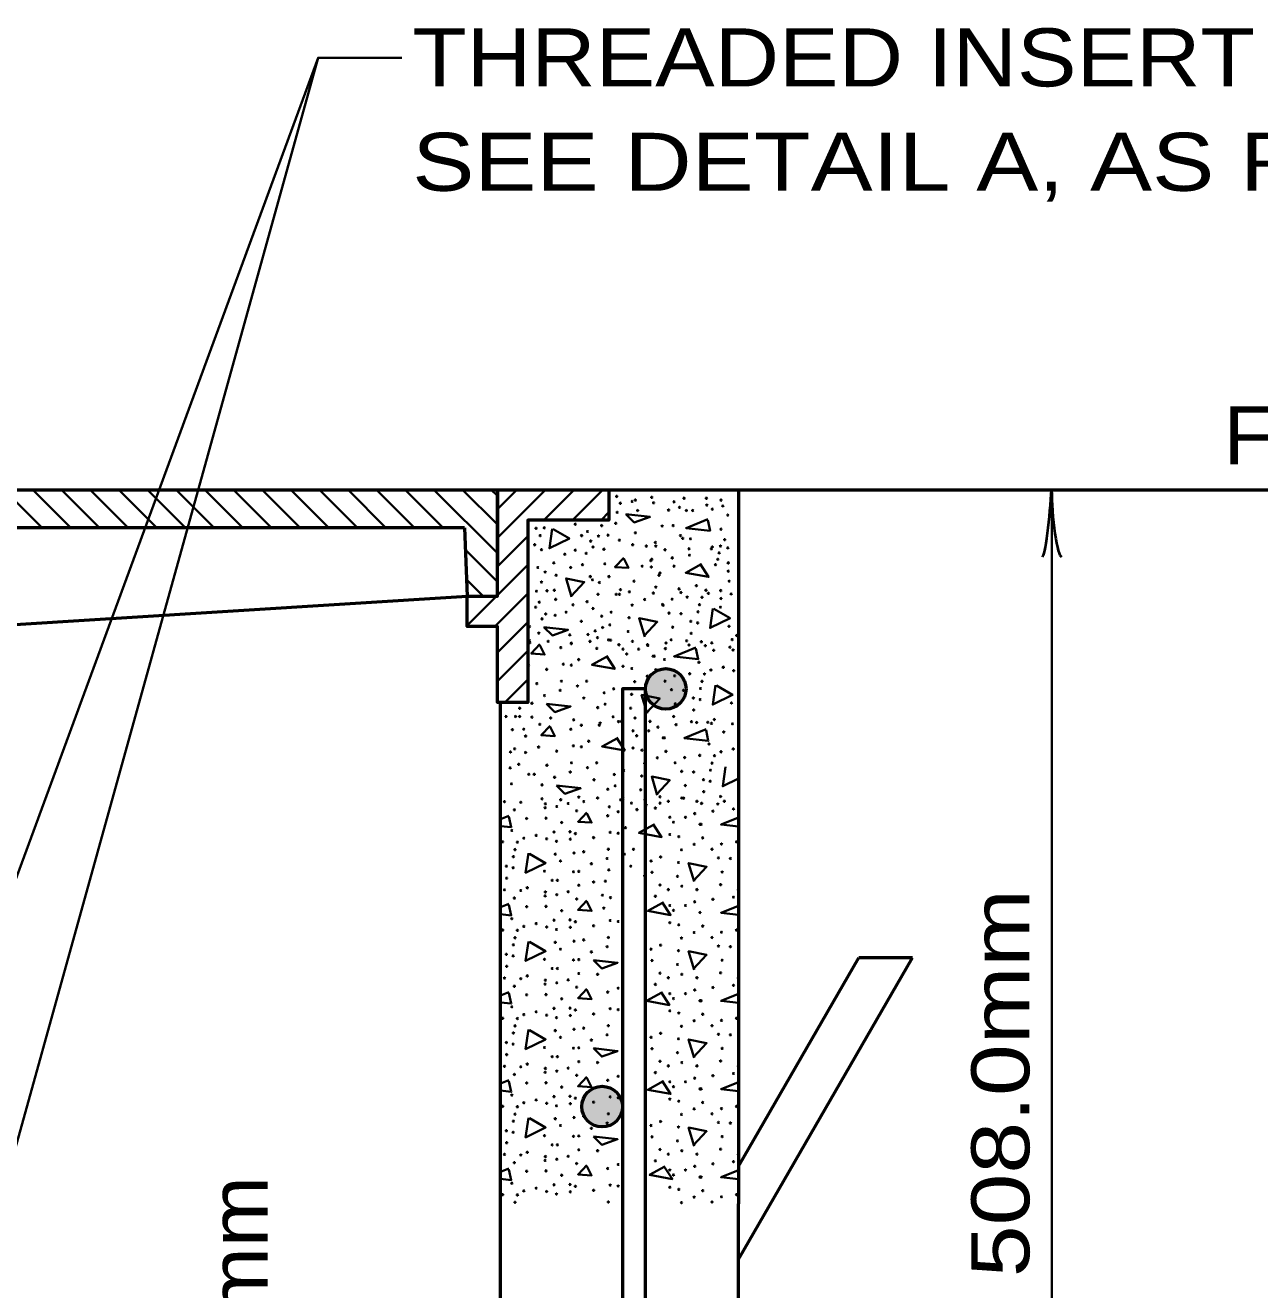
# Model space of a CAD drawing. Extents: x 918 to 1774, y -8 to 536.
# Drawn here: x 1103.6 to 1167.4, y 193.7 to 259.1 of the extents above; entities that cross this region are included whole.
import ezdxf

# ---------------------------------------------------------------- set-up
doc = ezdxf.new("R2010")
doc.units = 0
doc.header["$LTSCALE"] = 1.2
doc.layers.add('1', color=7, linetype='Continuous', lineweight=35)

msp = doc.modelspace()

# ---------------------------------------------------------------- hatches: boundary and pattern name
at = {"layer": '1'}
for points in [[(1135.628, 224.745, 1), (1137.721, 224.745, 1)], [(1132.329, 203.145, 1), (1134.433, 203.145, 1)]]:
    msp.add_hatch(color=256, dxfattribs=at).paths.add_polyline_path(points)

# ---------------------------------------------------------------- linework, layer by layer
for p, q in [((1118.692, 257.384), (1123.028, 257.384)), ((1102.459, 235.047), (1104.424, 233.082)), ((1103.941, 235.047), (1105.905, 233.082)), ((1105.423, 235.047), (1107.387, 233.082)), ((1106.905, 235.047), (1108.87, 233.082)), ((1108.387, 235.047), (1110.351, 233.082)), ((1109.868, 235.047), (1111.833, 233.082)), ((1111.351, 235.047), (1113.315, 233.082)), ((1112.832, 235.047), (1114.797, 233.082)), ((1114.314, 235.047), (1116.279, 233.082)), ((1115.796, 235.047), (1117.761, 233.082)), ((1117.278, 235.047), (1119.243, 233.082)), ((1118.76, 235.047), (1120.725, 233.082)), ((1120.243, 235.047), (1122.207, 233.082)), ((1121.724, 235.047), (1123.689, 233.082)), ((1123.206, 235.047), (1125.171, 233.082)), ((1124.688, 235.047), (1127.967, 231.768)), ((1126.17, 235.047), (1127.967, 233.25)), ((1127.653, 235.047), (1127.967, 234.731)), ((1127.967, 234.04), (1128.974, 235.047)), ((1127.967, 232.558), (1130.456, 235.047)), ((1130.366, 233.475), (1131.938, 235.047)), ((1131.848, 233.475), (1133.42, 235.047)), ((1133.33, 233.475), (1133.731, 233.876)), ((1127.967, 231.076), (1129.539, 232.648)), ((1126.303, 231.95), (1127.967, 230.285)), ((1127.967, 229.594), (1129.539, 231.166)), ((1126.362, 230.408), (1127.226, 229.545)), ((1126.396, 228.022), (1127.918, 229.545)), ((1127.828, 227.973), (1129.539, 229.684)), ((1127.967, 226.63), (1129.539, 228.202)), ((1127.967, 225.148), (1129.539, 226.72)), ((1128.345, 224.043), (1129.539, 225.238)), ((1128.563, 218.189), (1128.128, 218.013)), ((1128.563, 213.629), (1128.128, 213.453)), ((1128.563, 209.069), (1128.128, 208.893)), ((1128.563, 204.509), (1128.128, 204.333)), ((1128.563, 199.949), (1128.128, 199.773))]:
    msp.add_line(p, q, dxfattribs=at)
at = {"layer": '1', "lineweight": 53}
for p, q in [((1072.952, 235.047), (1127.967, 235.047)), ((1127.967, 235.047), (1140.428, 235.047)), ((1127.967, 235.047), (1127.967, 231.117)), ((1140.428, 235.047), (1140.428, 198.122)), ((1140.428, 235.047), (1199.62, 235.047)), ((1126.26, 233.082), (1126.396, 229.545)), ((1101.426, 227.973), (1126.396, 229.545)), ((1128.128, 198.122), (1128.128, 224.043)), ((1140.428, 195.243), (1149.428, 210.843)), ((1140.428, 200.046), (1146.657, 210.843)), ((1149.428, 210.843), (1146.657, 210.843)), ((1128.128, 159.172), (1128.128, 198.122)), ((1140.428, 159.172), (1140.428, 198.122))]:
    msp.add_line(p, q, dxfattribs=at)
at = {"layer": '1'}
for points in [[(1101.54, 210.795), (1118.692, 257.384), (1101.575, 195.743)], [(1156.628, 235.047), (1156.628, 170.643), (1156.628, 158.067), (1156.628, 146.075), (1156.628, 108.575)], [(1138.849, 233.52), (1137.721, 233.064), (1138.968, 232.92), (1138.849, 233.472)], [(1130.848, 233.003), (1131.688, 232.523), (1130.656, 232.019), (1130.8, 233.027)], [(1134.504, 231.528), (1134.048, 231.048), (1134.744, 231), (1134.504, 231.48)], [(1138.502, 231.187), (1137.71, 230.755), (1138.886, 230.539), (1138.454, 231.211)], [(1131.807, 229.5), (1131.519, 230.46), (1132.455, 230.268), (1131.783, 229.548)], [(1139.161, 228.881), (1140.001, 228.401), (1138.969, 227.897), (1139.113, 228.905)], [(1135.585, 227.441), (1135.297, 228.401), (1136.233, 228.209), (1135.561, 227.489)], [(1130.17, 227.052), (1129.715, 226.572), (1130.41, 226.524), (1130.17, 227.004)], [(1138.235, 226.884), (1137.107, 226.428), (1138.355, 226.284), (1138.235, 226.836)], [(1133.65, 226.428), (1132.859, 225.996), (1134.034, 225.78), (1133.602, 226.452)], [(1139.291, 224.916), (1140.13, 224.436), (1139.099, 223.932), (1139.243, 224.94)], [(1135.715, 223.476), (1135.427, 224.436), (1136.362, 224.244), (1135.691, 223.524)], [(1130.69, 222.828), (1130.234, 222.348), (1130.93, 222.3), (1130.69, 222.78)], [(1138.754, 222.66), (1137.626, 222.204), (1138.874, 222.06), (1138.754, 222.612)], [(1134.17, 222.204), (1133.378, 221.772), (1134.554, 221.556), (1134.122, 222.228)], [(1140.428, 220.104), (1139.618, 219.708), (1139.762, 220.716)], [(1136.234, 219.252), (1135.946, 220.212), (1136.882, 220.02), (1136.21, 219.3)], [(1128.128, 217.653), (1128.683, 217.589), (1128.563, 218.141)], [(1132.595, 218.357), (1132.139, 217.877), (1132.835, 217.829), (1132.595, 218.309)], [(1136.075, 217.733), (1135.283, 217.301), (1136.459, 217.085), (1136.027, 217.757)], [(1140.428, 218.095), (1139.531, 217.733), (1140.428, 217.629)], [(1129.619, 216.221), (1130.459, 215.741), (1129.427, 215.237), (1129.571, 216.245)], [(1138.139, 214.781), (1137.851, 215.741), (1138.787, 215.549), (1138.115, 214.829)], [(1128.128, 213.093), (1128.683, 213.029), (1128.563, 213.581)], [(1132.595, 213.797), (1132.139, 213.317), (1132.835, 213.269), (1132.595, 213.749)], [(1136.536, 213.696), (1135.744, 213.264), (1136.92, 213.048), (1136.488, 213.72)], [(1140.428, 213.535), (1139.531, 213.173), (1140.428, 213.069)], [(1129.619, 211.661), (1130.459, 211.181), (1129.427, 210.677), (1129.571, 211.685)], [(1138.139, 210.221), (1137.851, 211.181), (1138.787, 210.989), (1138.115, 210.269)], [(1132.595, 209.237), (1132.139, 208.757), (1132.835, 208.709), (1132.595, 209.189)], [(1128.128, 208.533), (1128.683, 208.469), (1128.563, 209.021)], [(1136.475, 209.044), (1135.683, 208.612), (1136.859, 208.396), (1136.427, 209.068)], [(1140.428, 208.975), (1139.531, 208.613), (1140.428, 208.509)], [(1129.619, 207.101), (1130.459, 206.621), (1129.427, 206.117), (1129.571, 207.125)], [(1138.139, 205.661), (1137.851, 206.621), (1138.787, 206.429), (1138.115, 205.709)], [(1132.595, 204.677), (1132.139, 204.197), (1132.835, 204.149), (1132.595, 204.629)], [(1128.128, 203.973), (1128.683, 203.909), (1128.563, 204.461)], [(1136.536, 204.453), (1135.744, 204.021), (1136.92, 203.805), (1136.488, 204.477)], [(1140.428, 204.415), (1139.531, 204.053), (1140.428, 203.949)], [(1129.619, 202.541), (1130.459, 202.061), (1129.427, 201.557), (1129.571, 202.565)], [(1138.139, 201.101), (1137.851, 202.061), (1138.787, 201.869), (1138.115, 201.149)], [(1132.595, 200.117), (1132.139, 199.637), (1132.835, 199.589), (1132.595, 200.069)], [(1128.128, 199.413), (1128.683, 199.349), (1128.563, 199.901)], [(1136.629, 200.047), (1135.837, 199.615), (1137.013, 199.399), (1136.581, 200.071)], [(1140.428, 199.855), (1139.531, 199.493), (1140.428, 199.389)]]:
    msp.add_lwpolyline(points, dxfattribs=at)
at = {"layer": '1', "lineweight": 53}
for points in [[(1133.731, 235.047), (1133.731, 233.475), (1129.539, 233.475), (1129.539, 224.043), (1127.967, 224.043), (1127.967, 227.973), (1126.396, 227.973), (1126.396, 229.545), (1127.967, 229.545), (1127.967, 235.047)], [(1126.26, 233.082), (1101.778, 233.082), (1101.426, 227.973), (1099.493, 227.973), (1099.141, 233.082)]]:
    msp.add_lwpolyline(points, dxfattribs=at)
at = {"layer": '1'}
for points in [[(1134.616, 233.787), (1135.864, 233.643), (1135.048, 233.355)], [(1130.377, 227.945), (1131.625, 227.8), (1130.809, 227.513)], [(1130.506, 223.98), (1131.755, 223.836), (1130.938, 223.548)], [(1131.026, 219.756), (1132.274, 219.612), (1131.458, 219.324)], [(1132.931, 210.725), (1134.179, 210.581), (1133.363, 210.293)], [(1132.931, 206.165), (1134.179, 206.021), (1133.363, 205.733)], [(1132.931, 201.605), (1134.179, 201.461), (1133.363, 201.173)]]:
    msp.add_lwpolyline(points, close=True, dxfattribs=at)
at = {"layer": '1', "lineweight": 53}
msp.add_lwpolyline([(1135.628, 152.043), (1135.628, 224.745), (1134.428, 224.745), (1134.428, 153.243), (1110.428, 153.243), (1110.428, 152.043)], close=True, dxfattribs=at)
at = {"layer": '1'}
for centre in [(1134.136, 234.698), (1134.324, 234.345), (1134.936, 234.439), (1135.101, 234.51), (1135.949, 234.651), (1136.043, 234.369), (1137.103, 234.416), (1137.385, 234.133), (1137.621, 234.604), (1138.775, 234.604), (1138.798, 234.251), (1139.528, 234.51), (1139.623, 234.204), (1134.159, 233.874), (1135.219, 233.968), (1136.82, 233.992), (1137.739, 233.968), (1138.068, 233.968), (1139.081, 234.039), (1139.882, 233.732), (1129.967, 233.049), (1130.391, 233.073), (1131.993, 233.261), (1132.628, 232.884), (1133.358, 233.191), (1134.088, 233.308), (1135.101, 232.814), (1136.49, 233.167), (1137.056, 233.191), (1139.528, 233.002), (1129.897, 232.201), (1130.179, 232.672), (1132.322, 232.672), (1132.793, 232.39), (1132.911, 232.083), (1133.194, 232.649), (1133.688, 232.696), (1134.277, 232.437), (1134.96, 232.201), (1135.666, 232.131), (1136.137, 232.319), (1136.161, 232.131), (1137.432, 232.672), (1137.55, 232.531), (1137.951, 232.508), (1139.081, 232.083), (1139.505, 232.131), (1139.717, 232.46), (1130.25, 231.942), (1131.451, 231.707), (1131.993, 231.919), (1132.558, 231.754), (1133.476, 231.966), (1135.949, 231.447), (1136.632, 231.942), (1137.009, 231.518), (1137.88, 231.989), (1137.903, 231.659), (1139.034, 231.989), (1139.364, 231.447), (1139.434, 231.777), (1139.882, 232.036), (1130.061, 231.023), (1130.438, 230.788), (1130.886, 231.259), (1131.757, 231.023), (1132.369, 231.165), (1133.523, 231.212), (1135.454, 231.094), (1135.902, 231.377), (1135.925, 231.047), (1137.103, 231.094), (1139.246, 231.165), (1139.905, 231.259), (1139.905, 230.835), (1130.25, 230.27), (1131.003, 230.623), (1132.77, 230.552), (1132.887, 230.387), (1133.241, 230.246), (1133.735, 230.552), (1135.03, 230.317), (1136.326, 230.623), (1136.373, 230.741), (1139.952, 230.317), (1129.991, 229.798), (1130.532, 229.822), (1130.909, 229.846), (1133.17, 229.633), (1134.112, 229.633), (1134.277, 229.633), (1134.33, 229.876), (1134.791, 229.765), (1136.032, 229.701), (1136.161, 230.01), (1137.362, 229.916), (1137.456, 229.728), (1137.781, 229.494), (1138.258, 230.083), (1138.545, 229.478), (1138.751, 229.846), (1138.879, 229.685), (1139.515, 229.828), (1140.056, 229.653), (1129.944, 228.974), (1130.132, 229.233), (1130.98, 229.374), (1131.875, 229.092), (1132.605, 229.257), (1132.911, 228.903), (1134.934, 229.081), (1135.587, 229.367), (1136.509, 229.112), (1136.538, 229.068), (1137.002, 229.383), (1138.417, 229.097), (1139.505, 228.974), (1139.528, 229.421), (1130.275, 228.365), (1130.462, 228.621), (1130.956, 228.55), (1131.522, 228.715), (1132.31, 228.237), (1133.36, 228.508), (1133.853, 228.715), (1134.775, 228.428), (1136.843, 228.667), (1137.463, 228.635), (1137.972, 228.237), (1138.322, 228.158), (1138.338, 228.731), (1129.623, 227.967), (1130.109, 227.631), (1131.71, 227.537), (1132.652, 227.56), (1133.026, 227.744), (1133.408, 227.919), (1133.782, 228.055), (1134.728, 227.712), (1137.034, 227.935), (1137.988, 227.617), (1139.944, 227.983), (1140.342, 227.506), (1129.623, 227.251), (1129.641, 227.137), (1130.593, 227.203), (1131.247, 226.882), (1131.786, 227.108), (1131.788, 227.089), (1132.758, 227.201), (1133.146, 227.396), (1133.713, 227.28), (1133.821, 227.267), (1134.251, 227.028), (1134.95, 227.203), (1135.73, 227.028), (1135.748, 226.994), (1136.687, 227.121), (1136.954, 227.283), (1137.752, 227.232), (1137.877, 227.013), (1138.515, 227.185), (1138.72, 226.981), (1139.054, 227.124), (1139.992, 226.901), (1140.106, 227.296), (1132.17, 226.262), (1133.106, 226.838), (1134.46, 226.803), (1134.651, 226.548), (1135.271, 226.803), (1136.019, 226.437), (1136.082, 226.437), (1136.608, 226.265), (1136.655, 226.83), (1139.152, 226.739), (1140.154, 226.755), (1129.578, 225.96), (1130.516, 225.753), (1131.375, 226.023), (1131.788, 225.976), (1134.46, 225.912), (1134.921, 225.801), (1136.162, 225.737), (1138.388, 226.119), (1139.008, 225.721), (1139.645, 225.864), (1140.185, 225.689), (1130.007, 225.021), (1131.279, 225.148), (1132.106, 224.894), (1132.583, 225.148), (1135.064, 225.117), (1135.716, 225.403), (1136.639, 225.148), (1137.132, 225.419), (1137.911, 225.53), (1138.547, 225.132), (1138.675, 225.514), (1130.405, 224.401), (1131.216, 224.671), (1132.44, 224.273), (1133.49, 224.544), (1133.983, 224.751), (1134.905, 224.464), (1136.973, 224.703), (1137.593, 224.671), (1138.102, 224.273), (1138.468, 224.767), (1129.119, 223.744), (1129.753, 224.003), (1133.156, 223.78), (1133.538, 223.955), (1134.858, 223.748), (1137.164, 223.971), (1138.118, 223.653), (1138.452, 224.194), (1140.074, 224.019), (1128.413, 223.32), (1128.907, 223.32), (1129.119, 223.32), (1129.753, 223.287), (1130.723, 223.239), (1131.915, 223.144), (1133.278, 222.977), (1133.951, 223.303), (1134.232, 223.056), (1134.381, 223.064), (1135.08, 223.239), (1135.86, 223.064), (1137.084, 223.319), (1138.007, 223.048), (1138.272, 223.008), (1138.85, 223.017), (1139.035, 222.961), (1139.183, 223.16), (1140.122, 222.937), (1128.743, 222.637), (1129.331, 222.661), (1129.426, 222.307), (1130.161, 222.913), (1131.767, 222.658), (1132.308, 222.865), (1133.235, 222.873), (1134.98, 222.579), (1135.171, 222.324), (1135.791, 222.579), (1136.268, 222.77), (1137.206, 222.897), (1139.671, 222.515), (1128.86, 221.648), (1130.097, 221.736), (1131.894, 221.799), (1132.308, 221.752), (1132.69, 222.038), (1134.98, 221.688), (1136.538, 222.213), (1136.602, 222.213), (1138.908, 221.895), (1140.164, 221.64), (1128.648, 221.483), (1129.426, 221.459), (1131.036, 221.529), (1135.441, 221.577), (1136.236, 221.179), (1136.682, 221.513), (1137.652, 221.195), (1138.431, 221.306), (1139.194, 221.29), (1139.528, 221.497), (1128.625, 220.658), (1129.072, 220.847), (1129.59, 220.328), (1129.873, 220.328), (1130.527, 220.797), (1131.736, 220.447), (1131.799, 220.924), (1132.626, 220.67), (1133.103, 220.924), (1134.01, 220.32), (1134.503, 220.527), (1135.584, 220.893), (1137.159, 220.924), (1137.493, 220.479), (1138.113, 220.447), (1138.988, 220.543), (1139.067, 220.908), (1128.696, 219.834), (1130.272, 219.779), (1130.924, 220.177), (1132.96, 220.049), (1134.057, 219.731), (1135.425, 220.24), (1137.683, 219.747), (1138.622, 220.049), (1138.972, 219.97), (1130.272, 219.063), (1131.243, 219.015), (1132.177, 219.151), (1133.147, 219.104), (1133.676, 219.556), (1134.34, 219.008), (1134.471, 219.079), (1135.377, 219.524), (1135.6, 219.015), (1136.375, 219.167), (1137.505, 219.104), (1137.604, 219.095), (1138.638, 219.429), (1139.508, 219.183), (1128.335, 218.913), (1128.844, 218.489), (1129.178, 218.881), (1130.434, 218.6), (1130.45, 218.801), (1131.038, 218.664), (1131.627, 218.817), (1132.066, 218.441), (1132.435, 218.92), (1133.755, 218.649), (1134.213, 218.393), (1134.9, 218.84), (1135.183, 218.505), (1135.66, 218.738), (1136.137, 218.584), (1136.379, 218.84), (1136.805, 218.929), (1138.284, 218.929), (1138.526, 218.824), (1139.111, 218.425), (1139.369, 218.793), (1139.703, 218.936), (1140.176, 218.537), (1129.48, 218.044), (1130.482, 218.059), (1131.293, 217.837), (1133.672, 218.187), (1136.884, 218.107), (1137.075, 217.853), (1137.695, 218.107), (1138.173, 218.298), (1138.443, 217.741), (1138.507, 217.741), (1128.717, 217.423), (1129.973, 217.169), (1130.895, 217.344), (1131.722, 217.359), (1132.002, 217.264), (1132.94, 217.057), (1133.799, 217.328), (1134.213, 217.28), (1134.594, 217.566), (1136.884, 217.216), (1137.346, 217.105), (1138.586, 217.041), (1128.239, 216.835), (1128.876, 216.437), (1129.003, 216.819), (1129.337, 217.025), (1130.514, 216.994), (1131.023, 216.866), (1131.738, 216.978), (1133.704, 216.453), (1135.008, 216.453), (1137.489, 216.421), (1138.141, 216.707), (1139.063, 216.453), (1139.556, 216.723), (1140.335, 216.835), (1128.796, 216.071), (1130.959, 216.198), (1131.229, 215.848), (1131.929, 216.262), (1132.431, 216.325), (1133.64, 215.975), (1134.531, 216.198), (1135.914, 215.848), (1136.407, 216.055), (1137.33, 215.769), (1139.397, 216.007), (1140.017, 215.975), (1128.43, 215.578), (1128.78, 215.498), (1130.402, 215.323), (1131.905, 215.289), (1132.177, 215.307), (1132.829, 215.705), (1133.732, 215.385), (1134.865, 215.578), (1135.58, 215.085), (1135.962, 215.26), (1139.588, 215.275), (1128.446, 214.957), (1129.512, 214.464), (1130.8, 214.846), (1131.07, 214.846), (1132.177, 214.591), (1132.94, 214.76), (1133.551, 214.801), (1136.375, 214.607), (1137.282, 215.053), (1137.505, 214.544), (1139.508, 214.623), (1128.335, 214.353), (1128.844, 213.929), (1129.178, 214.321), (1130.434, 214.04), (1130.45, 214.241), (1131.038, 214.104), (1131.627, 214.257), (1132.066, 213.881), (1133.399, 214.079), (1133.815, 213.954), (1136.137, 214.024), (1136.805, 214.369), (1138.284, 214.369), (1139.111, 213.865), (1140.176, 213.977), (1129.48, 213.484), (1130.482, 213.499), (1131.293, 213.277), (1133.468, 213.411), (1136.884, 213.547), (1137.075, 213.293), (1137.695, 213.547), (1138.173, 213.738), (1138.443, 213.181), (1128.717, 212.863), (1129.337, 212.465), (1129.973, 212.609), (1130.895, 212.784), (1131.722, 212.799), (1132.002, 212.704), (1132.94, 212.497), (1133.799, 212.768), (1134.213, 212.72), (1136.884, 212.656), (1137.346, 212.545), (1138.586, 212.481), (1128.239, 212.275), (1128.876, 211.877), (1129.003, 212.259), (1130.514, 212.434), (1131.023, 212.306), (1131.738, 212.418), (1133.704, 211.893), (1137.489, 211.861), (1138.141, 212.147), (1139.063, 211.893), (1139.556, 212.163), (1140.335, 212.275), (1128.796, 211.511), (1130.959, 211.638), (1131.229, 211.288), (1131.929, 211.702), (1132.431, 211.765), (1133.64, 211.415), (1135.914, 211.288), (1136.407, 211.495), (1137.33, 211.209), (1139.397, 211.447), (1140.017, 211.415), (1128.43, 211.018), (1128.78, 210.938), (1130.402, 210.763), (1131.905, 210.729), (1132.177, 210.747), (1132.829, 211.145), (1135.962, 210.7), (1139.588, 210.715), (1128.446, 210.397), (1129.512, 209.904), (1130.8, 210.286), (1131.07, 210.286), (1132.177, 210.031), (1133.147, 209.984), (1136.375, 210.047), (1137.282, 210.493), (1137.505, 209.984), (1139.508, 210.063), (1128.335, 209.793), (1128.844, 209.369), (1129.178, 209.761), (1130.434, 209.48), (1130.45, 209.681), (1131.038, 209.544), (1131.627, 209.697), (1132.066, 209.321), (1134.213, 209.273), (1136.137, 209.464), (1136.805, 209.809), (1138.284, 209.809), (1139.111, 209.305), (1140.176, 209.417), (1129.48, 208.924), (1130.482, 208.939), (1131.293, 208.717), (1133.672, 209.067), (1136.884, 208.987), (1137.075, 208.733), (1137.695, 208.987), (1138.173, 209.178), (1138.443, 208.621), (1138.507, 208.621), (1128.717, 208.303), (1129.337, 207.905), (1129.973, 208.049), (1130.895, 208.224), (1131.722, 208.239), (1132.002, 208.144), (1132.94, 207.937), (1133.799, 208.208), (1134.213, 208.16), (1136.884, 208.096), (1137.346, 207.985), (1138.586, 207.921), (1128.239, 207.715), (1128.876, 207.317), (1129.003, 207.699), (1130.514, 207.874), (1131.023, 207.746), (1131.738, 207.858), (1133.704, 207.333), (1137.489, 207.301), (1138.141, 207.587), (1139.063, 207.333), (1139.556, 207.603), (1140.335, 207.715), (1128.796, 206.951), (1130.959, 207.078), (1131.229, 206.728), (1131.929, 207.142), (1132.431, 207.205), (1132.829, 206.585), (1133.64, 206.855), (1135.914, 206.728), (1136.407, 206.935), (1137.33, 206.649), (1139.397, 206.887), (1140.017, 206.855), (1128.43, 206.458), (1128.78, 206.378), (1130.402, 206.203), (1131.905, 206.169), (1132.177, 206.187), (1135.962, 206.14), (1137.282, 205.933), (1139.588, 206.155), (1128.446, 205.837), (1129.512, 205.344), (1130.8, 205.726), (1131.07, 205.726), (1132.177, 205.471), (1133.147, 205.424), (1136.375, 205.487), (1137.505, 205.424), (1139.508, 205.503), (1128.335, 205.233), (1128.844, 204.809), (1129.178, 205.201), (1130.434, 204.92), (1130.45, 205.121), (1131.038, 204.984), (1131.627, 205.137), (1132.066, 204.761), (1134.213, 204.713), (1136.137, 204.904), (1136.805, 205.249), (1138.173, 204.618), (1138.284, 205.249), (1139.111, 204.745), (1140.176, 204.857), (1129.48, 204.364), (1130.482, 204.379), (1131.293, 204.157), (1133.672, 204.507), (1136.884, 204.427), (1137.075, 204.173), (1137.695, 204.427), (1138.443, 204.061), (1138.507, 204.061), (1128.717, 203.743), (1129.337, 203.345), (1129.973, 203.489), (1130.514, 203.314), (1130.895, 203.664), (1131.722, 203.679), (1132.002, 203.584), (1132.94, 203.377), (1133.799, 203.648), (1134.213, 203.6), (1136.884, 203.536), (1137.346, 203.425), (1138.586, 203.361), (1128.239, 203.155), (1128.876, 202.757), (1129.003, 203.139), (1131.023, 203.186), (1131.738, 203.298), (1133.704, 202.773), (1137.489, 202.741), (1138.141, 203.027), (1139.063, 202.773), (1139.556, 203.043), (1140.335, 203.155), (1128.796, 202.391), (1130.959, 202.518), (1131.229, 202.168), (1131.929, 202.582), (1132.431, 202.645), (1132.829, 202.025), (1133.64, 202.295), (1135.914, 202.168), (1136.407, 202.375), (1137.33, 202.089), (1139.397, 202.327), (1140.017, 202.295), (1128.43, 201.898), (1128.78, 201.818), (1130.402, 201.643), (1131.905, 201.609), (1132.177, 201.627), (1135.962, 201.58), (1137.282, 201.373), (1139.588, 201.595), (1128.446, 201.277), (1129.512, 200.784), (1130.8, 201.166), (1131.07, 201.166), (1132.177, 200.911), (1133.147, 200.864), (1136.375, 200.927), (1137.505, 200.864), (1139.508, 200.943), (1128.335, 200.673), (1128.844, 200.249), (1129.178, 200.641), (1130.434, 200.36), (1130.45, 200.561), (1131.038, 200.424), (1131.627, 200.577), (1132.066, 200.201), (1134.213, 200.153), (1136.137, 200.344), (1136.805, 200.689), (1138.173, 200.058), (1138.284, 200.689), (1139.111, 200.185), (1140.176, 200.297), (1129.48, 199.804), (1130.482, 199.819), (1131.293, 199.597), (1133.672, 199.947), (1136.884, 199.867), (1137.075, 199.613), (1137.695, 199.867), (1138.443, 199.501), (1138.507, 199.501), (1128.717, 199.183), (1129.337, 198.785), (1129.973, 198.929), (1130.514, 198.754), (1130.895, 199.104), (1131.722, 199.119), (1131.738, 198.738), (1132.002, 199.024), (1132.94, 198.817), (1133.799, 199.088), (1134.213, 199.04), (1136.884, 198.976), (1137.346, 198.865), (1138.586, 198.801), (1128.239, 198.595), (1128.876, 198.197), (1129.003, 198.579), (1131.023, 198.626), (1133.704, 198.213), (1137.489, 198.181), (1138.141, 198.467), (1139.063, 198.213), (1139.556, 198.483), (1140.335, 198.595)]:
    msp.add_circle(centre, 0.0318, dxfattribs=at)
at = {"layer": '1', "lineweight": 53}
for centre, radius in [((1136.674, 224.745), 1.047), ((1133.381, 203.145), 1.052)]:
    msp.add_circle(centre, radius, dxfattribs=at)
at = {"layer": '1'}
for centre in [(1140.431, 214.353), (1140.431, 209.793), (1140.431, 205.233), (1140.431, 200.673)]:
    msp.add_arc(centre, 0.0318, 96.18313, 263.81687, dxfattribs=at)
at = {"layer": '1', "lineweight": 40}
for centre, major_axis, ratio, start_param, end_param in [((1156.364, 233.691), (0.211, 2.108), 0.07063, 3.140715, 5.41811), ((1156.949, 233.726), (-0.187, 2.143), 0.122415, 0.896353, 3.141593)]:
    msp.add_ellipse(centre, major_axis=major_axis, ratio=ratio, start_param=start_param, end_param=end_param, dxfattribs=at)

# ---------------------------------------------------------------- texts
at = {"layer": '1'}
for s, width, p in [('THREADED INSERT (TYP.)', 1.15, (1123.565, 255.901)), ("SEE DETAIL A, AS REQ'D. 2 SETS MIN.", 1.2, (1123.565, 250.501)), ('FINISH GRADE', 1.05, (1165.525, 236.359))]:
    msp.add_text(s, height=3, dxfattribs=dict(at, width=width)).set_placement(p)
for s, width, p in [('508.0mm', 1.2, (1155.474, 194.326)), ('150mm', 1.1, (1116.081, 184.837))]:
    msp.add_text(s, height=3, rotation=90, dxfattribs=dict(at, width=width)).set_placement(p)

doc.saveas('drawing.dxf')
